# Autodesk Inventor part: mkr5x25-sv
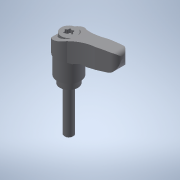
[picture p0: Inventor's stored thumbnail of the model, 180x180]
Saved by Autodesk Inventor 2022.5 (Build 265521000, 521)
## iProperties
Created: 2017-09
Part Number: mkr5x25-sv
Material: 一般
Document SubType Name: Modeling
Designer: imaocorp
Density: 1 g/cm^3
Appearance: 既定
Author: imaocorp
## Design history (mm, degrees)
node "mkr5x25-sv.x_t1"
node "mkr5x25-sv"
node "Base1"
